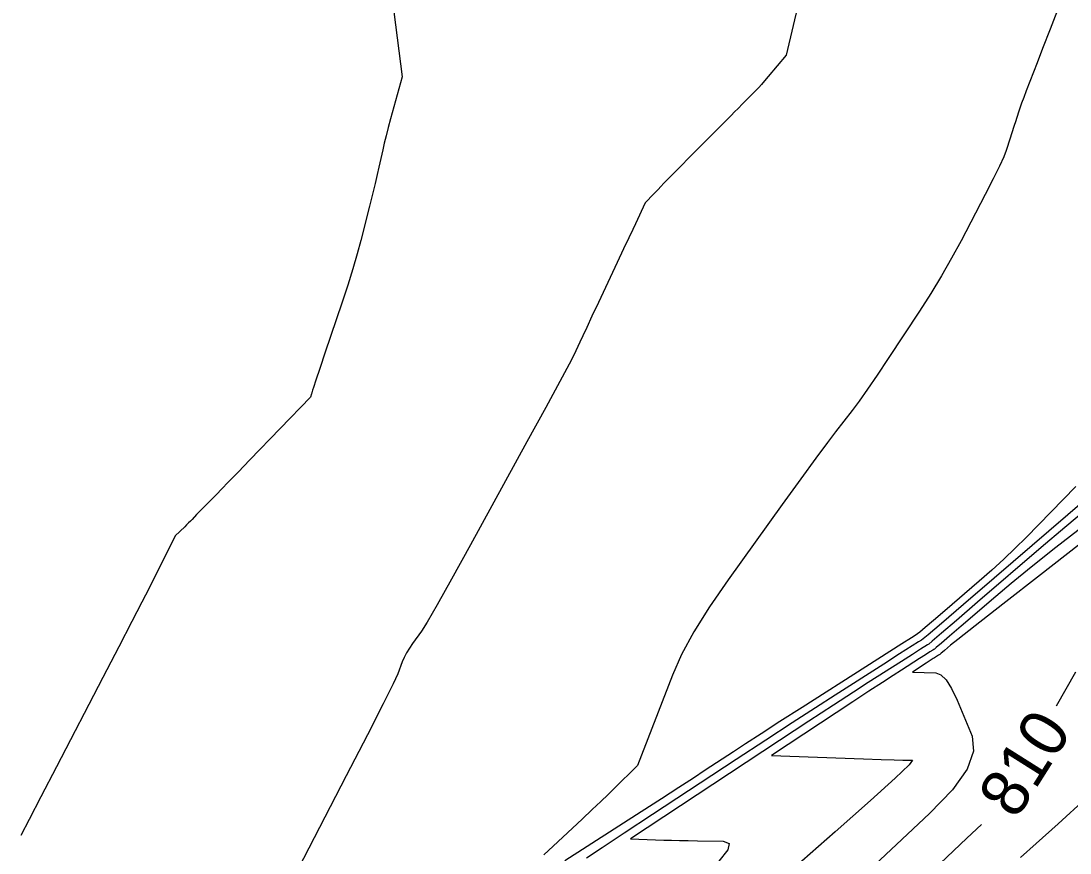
# Model space of a CAD drawing. Extents: x 2079879 to 2092887, y 778083 to 784051.
# Drawn here: x 2084103 to 2084164.7, y 780983.2 to 781032.2 of the extents above; entities that cross this region are included whole.
import ezdxf

# ---------------------------------------------------------------- set-up
doc = ezdxf.new("R2010")
doc.units = 0
doc.layers.add('DT_X_Contour_Major', color=7, linetype='Continuous')
doc.layers.add('DT_X_Contour_Minor', color=7, linetype='Continuous')

msp = doc.modelspace()

# ---------------------------------------------------------------- linework, layer by layer
at = {"layer": 'DT_X_Contour_Major'}
for points in [[(2084165, 781004.775), (2084162.075, 781001.78), (2084161.432, 781001.137), (2084160.757, 781000.493), (2084160.05, 780999.846), (2084159.312, 780999.197), (2084157.299, 780997.465), (2084156.633, 780996.893), (2084156.142, 780996.474), (2084155.826, 780996.21), (2084155.686, 780996.1), (2084155.548, 780996.012), (2084155.328, 780995.871), (2084154.769, 780995.515), (2084152.641, 780994.157), (2084148.902, 780991.771), (2084147.598, 780990.938), (2084146.489, 780990.225), (2084145.576, 780989.635), (2084144.859, 780989.165), (2084143.206, 780988.076), (2084142.506, 780987.617), (2084141.643, 780987.056), (2084140.619, 780986.394), (2084139.433, 780985.629), (2084134.941, 780982.739)], [(2084164.981, 780993.857), (2084163.837, 780991.847)], [(2084159.441, 780984.879), (2084158.593, 780984.075), (2084157.019, 780982.582)]]:
    msp.add_lwpolyline(points, dxfattribs=at)
at = {"layer": 'DT_X_Contour_Minor'}
for points in [[(2084166.851, 781040.448), (2084163.478, 781031.683), (2084163.04, 781030.546), (2084162.715, 781029.7), (2084162.501, 781029.145), (2084162.08, 781028.052), (2084161.934, 781027.666), (2084161.81, 781027.33), (2084161.708, 781027.043), (2084161.629, 781026.806), (2084161.448, 781026.237), (2084161.377, 781026.017), (2084161.222, 781025.53), (2084161.137, 781025.264), (2084160.905, 781024.535), (2084160.762, 781024.169), (2084160.508, 781023.615), (2084160.142, 781022.875), (2084159.665, 781021.948), (2084158.245, 781019.228), (2084157.693, 781018.205), (2084157.101, 781017.175), (2084156.471, 781016.138), (2084155.801, 781015.095), (2084153.962, 781012.304), (2084153.312, 781011.328), (2084152.743, 781010.495), (2084152.253, 781009.804), (2084151.844, 781009.255), (2084150.859, 781007.982), (2084150.386, 781007.356), (2084149.708, 781006.435), (2084148.823, 781005.219), (2084147.732, 781003.707), (2084144.547, 780999.281), (2084143.447, 780997.686), (2084142.535, 780996.221), (2084141.812, 780994.886), (2084141.277, 780993.681), (2084139.221, 780988.359), (2084137.831, 780986.986), (2084137.49, 780986.654), (2084137.066, 780986.247), (2084136.556, 780985.764), (2084135.962, 780985.207), (2084134.264, 780983.621), (2084133.699, 780983.093)], [(2084124.586, 781035.019), (2084125.38, 781028.875), (2084124.696, 781026.4), (2084124.558, 781025.888), (2084124.435, 781025.413), (2084124.327, 781024.975), (2084124.235, 781024.574), (2084124.011, 781023.554), (2084123.913, 781023.124), (2084123.789, 781022.601), (2084123.637, 781021.984), (2084123.458, 781021.274), (2084122.944, 781019.254), (2084122.73, 781018.455), (2084122.473, 781017.575), (2084122.172, 781016.612), (2084121.828, 781015.566), (2084120.853, 781012.669), (2084120.532, 781011.715), (2084120.301, 781011.025), (2084120.159, 781010.601), (2084120.106, 781010.441), (2084120.086, 781010.367), (2084120.077, 781010.337), (2084120.068, 781010.304), (2084120.058, 781010.268), (2084120.047, 781010.228), (2084119.993, 781010.036), (2084116.425, 781006.338), (2084115.73, 781005.618), (2084115.172, 781005.042), (2084114.752, 781004.611), (2084114.471, 781004.325), (2084113.905, 781003.755), (2084113.706, 781003.555), (2084113.537, 781003.382), (2084113.395, 781003.237), (2084113.283, 781003.12), (2084113.02, 781002.842), (2084112.918, 781002.737), (2084112.812, 781002.629), (2084112.701, 781002.519), (2084112.585, 781002.405), (2084112.031, 781001.869), (2084110.491, 780998.798), (2084110.074, 780997.976), (2084109.483, 780996.825), (2084108.719, 780995.346), (2084107.781, 780993.539), (2084105.048, 780988.282), (2084104.132, 780986.519), (2084103.432, 780985.173), (2084102.948, 780984.244)], [(2084148.707, 781033.307), (2084147.961, 781030.161), (2084146.905, 781028.893), (2084146.692, 781028.64), (2084146.505, 781028.425), (2084146.344, 781028.247), (2084146.21, 781028.106), (2084145.886, 781027.78), (2084145.766, 781027.659), (2084145.647, 781027.54), (2084145.53, 781027.422), (2084145.415, 781027.306), (2084145.109, 781026.999), (2084144.949, 781026.838), (2084144.698, 781026.585), (2084144.355, 781026.24), (2084143.92, 781025.803), (2084142.639, 781024.516), (2084142.195, 781024.068), (2084141.822, 781023.691), (2084141.521, 781023.385), (2084141.292, 781023.15), (2084140.775, 781022.616), (2084140.592, 781022.427), (2084140.431, 781022.259), (2084140.292, 781022.114), (2084140.173, 781021.991), (2084139.673, 781021.467), (2084139.094, 781020.234), (2084138.934, 781019.893), (2084138.702, 781019.398), (2084138.397, 781018.749), (2084138.02, 781017.946), (2084136.919, 781015.6), (2084136.541, 781014.795), (2084136.233, 781014.138), (2084135.995, 781013.63), (2084135.826, 781013.27), (2084135.469, 781012.51), (2084135.196, 781011.977), (2084134.646, 781010.948), (2084133.819, 781009.423), (2084132.713, 781007.402), (2084129.396, 781001.351), (2084128.282, 780999.331), (2084127.431, 780997.81), (2084126.841, 780996.788), (2084126.513, 780996.265), (2084125.986, 780995.533), (2084125.801, 780995.26), (2084125.639, 780994.989), (2084125.501, 780994.72), (2084125.386, 780994.453), (2084125.113, 780993.745), (2084124.847, 780993.171), (2084124.254, 780991.98), (2084123.334, 780990.172), (2084122.087, 780987.746), (2084118.326, 780980.455)], [(2084169.626, 781004.819), (2084162.915, 780999.582), (2084160.696, 780997.85), (2084159.074, 780996.581), (2084158.05, 780995.774), (2084157.622, 780995.431), (2084157.276, 780995.134), (2084157.162, 780995.036), (2084157.08, 780994.966), (2084157.03, 780994.923), (2084157.012, 780994.908), (2084156.994, 780994.896), (2084156.967, 780994.879), (2084156.924, 780994.852), (2084156.865, 780994.814), (2084156.684, 780994.698), (2084156.603, 780994.646), (2084156.496, 780994.577), (2084156.362, 780994.489), (2084156.202, 780994.384), (2084155.394, 780993.851), (2084156.768, 780993.802), (2084157.067, 780993.694), (2084157.374, 780993.39), (2084157.691, 780992.89), (2084158.017, 780992.194), (2084158.896, 780990.078), (2084158.988, 780989.199), (2084158.602, 780988.149), (2084157.739, 780986.926), (2084156.4, 780985.533), (2084152.191, 780981.588)], [(2084165.64, 781004.067), (2084160.187, 780999.373), (2084158.393, 780997.829), (2084157.1, 780996.72), (2084156.308, 780996.044), (2084156.018, 780995.802), (2084155.912, 780995.735), (2084155.744, 780995.627), (2084154.636, 780994.921), (2084153.697, 780994.321), (2084150.848, 780992.503), (2084149.682, 780991.755), (2084148.323, 780990.873), (2084146.769, 780989.857), (2084145.022, 780988.709), (2084140.103, 780985.467), (2084138.441, 780984.373), (2084137.146, 780983.521), (2084136.217, 780982.913)], [(2084165.674, 781003.47), (2084164.347, 781002.364), (2084162.967, 781001.188), (2084159.217, 780997.96), (2084157.982, 780996.898), (2084157.093, 780996.135), (2084156.549, 780995.67), (2084156.349, 780995.504), (2084156.277, 780995.458), (2084155.868, 780995.197), (2084155.399, 780994.898), (2084154.753, 780994.485), (2084152.793, 780993.235), (2084151.915, 780992.67), (2084150.751, 780991.912), (2084149.301, 780990.963), (2084147.566, 780989.821), (2084138.797, 780984.042), (2084140.769, 780983.972), (2084141.21, 780983.958), (2084141.687, 780983.946), (2084142.199, 780983.937), (2084142.748, 780983.929), (2084144.259, 780983.913), (2084144.608, 780983.778), (2084144.521, 780983.386), (2084143.998, 780982.737)], [(2084165.541, 781002.527), (2084163.822, 781001.178), (2084162.374, 781000.025), (2084161.198, 780999.069), (2084160.294, 780998.31), (2084158.246, 780996.547), (2084157.572, 780995.967), (2084157.087, 780995.55), (2084156.789, 780995.297), (2084156.68, 780995.206), (2084156.641, 780995.18), (2084156.578, 780995.14), (2084156.418, 780995.038), (2084156.162, 780994.875), (2084155.809, 780994.649), (2084154.739, 780993.967), (2084154.259, 780993.658), (2084153.624, 780993.245), (2084152.832, 780992.726), (2084151.884, 780992.102), (2084147.096, 780988.947), (2084152.51, 780988.754), (2084153.54, 780988.718), (2084154.31, 780988.691), (2084154.82, 780988.675), (2084155.069, 780988.669), (2084155.388, 780988.665), (2084155.193, 780988.401), (2084154.371, 780987.612), (2084152.922, 780986.298), (2084150.845, 780984.458), (2084144.469, 780978.852)], [(2084165.583, 780986.409), (2084163.952, 780984.926), (2084162.673, 780983.771), (2084161.747, 780982.945)]]:
    msp.add_lwpolyline(points, dxfattribs=at)

# ---------------------------------------------------------------- texts
at = {"layer": 'DT_X_Contour_Major'}
msp.add_text('810', height=2.8, rotation=57.75885, dxfattribs=at).set_placement((2084161.485, 780985.114))

doc.saveas('drawing.dxf')
